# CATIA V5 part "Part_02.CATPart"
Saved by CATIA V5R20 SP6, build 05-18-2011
Part number: Part_02
Bounding box of the stored display mesh (mm): x -7 to 7, y -12 to 7, z -7 to 7
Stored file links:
  E:\#01 CATIA Lecture Materials\#16 3D Print Test\3D Print Test\7th Test\Part_02.CATPart
  E:\#01 CATIA Lecture Materials\#16 3D Print Test\3D Print Test\2nd Test\3D Print Test_02.CATProduct
  E:\#01 CATIA Lecture Materials\#16 3D Print Test\3D Print Test\7th Test\Part_01.CATPart
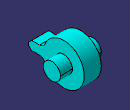
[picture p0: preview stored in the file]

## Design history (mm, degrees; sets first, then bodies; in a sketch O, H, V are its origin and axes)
Set1 "Reference Data"
  Point1 "Center Point": (0, 0, 0)
Body1 (main body)
Body2
  Sketch1 on yz-plane, origin (0, 0, 0), H (0, -1, 0), V (0, 0, 1)
    arc A1 centre (0, 0) radius 7 from (6.8374, 1.5) to (6.8374, -1.5) ccw
    line L1 (6.8374, 1.5) -> (12, 1.5)
    line L2 (12, 1.5) -> (12, -1.5)
    line L3 (12, -1.5) -> (6.8374, -1.5)
    radius A1 = 7
    distance V L2 = 12
    distance L1 L3 = 3
    horizontal: L1 H, L3 H
    vertical: L2 V
    symmetry: L1 L3 H
  Pad1: profile Sketch1, direction (-1, 0, 0), length 2.9, mirrored extent
  Fillet1: radius 2, on edge [face of Pad1 from Sketch1.A1 | face of Pad1 from Sketch1.L1]; edge [face of Pad1 from Sketch1.L3 | face of Pad1 from Sketch1.A1]
  Chamfer1: length 1, angle 45, on edge [face of Pad1 from Sketch1.L1 | face of Pad1 from Sketch1.L2]; edge [face of Pad1 from Sketch1.L2 | face of Pad1 from Sketch1.L3]
  Sketch2 on yz-plane, origin (0, 0, 0), H (0, -1, 0), V (0, 0, 1)
    circle A1 centre (0, 0) radius 2.9
    radius A1 = 2.9
  Pad2: profile Sketch2, direction (-1, 0, 0), length 7, mirrored extent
